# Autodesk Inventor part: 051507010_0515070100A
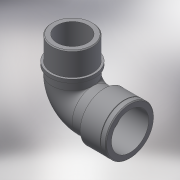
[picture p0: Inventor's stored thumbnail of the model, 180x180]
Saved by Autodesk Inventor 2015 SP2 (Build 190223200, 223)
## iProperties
Created: 2017-05
Part Number: 051507010_0515070100A
Material: Generic
Description: PLASSON 90° THREADED ELBOW MALE-FEMALE 1"-1"
Document SubType Name: Modeling
Designer: KIM
Mass: 35.7004 g
Surface Area: 178.919 cm^2
Volume: 35.7004 cm^3
Density: 1 g/cm^3
Appearance: Default
Author: KIM
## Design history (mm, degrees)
derived "051507.ipt"
feature "Solid1::051507.ipt"
tag "TaggingFeature1"
body "Solid1"
other parameters: "d0" = 47, "d1" = 45, "d2" = 0.5, "d3" = 0.5, "d4" = 39.3783, "d5" = 30.291, "d6" = 21, "d7" = 120 deg, "d8" = 25.2, "d9" = 4.2, "d10" = 33.47156, "d11" = 33.249, "d12" = 19, "d13" = 33.47156, "d14" = 24.93675, "d15" = 21.85, "d16" = 24.93675, "d19" = 0.66498, "d23" = 22.8, "d24" = 36.5739, "d25" = 0, "d26" = 0, "d27" = 20.9, "R_" = 33.249, "Rp_" = 30.291, "A_" = 45, "A_1" = 47, "l_" = 19, "l_1" = 21
